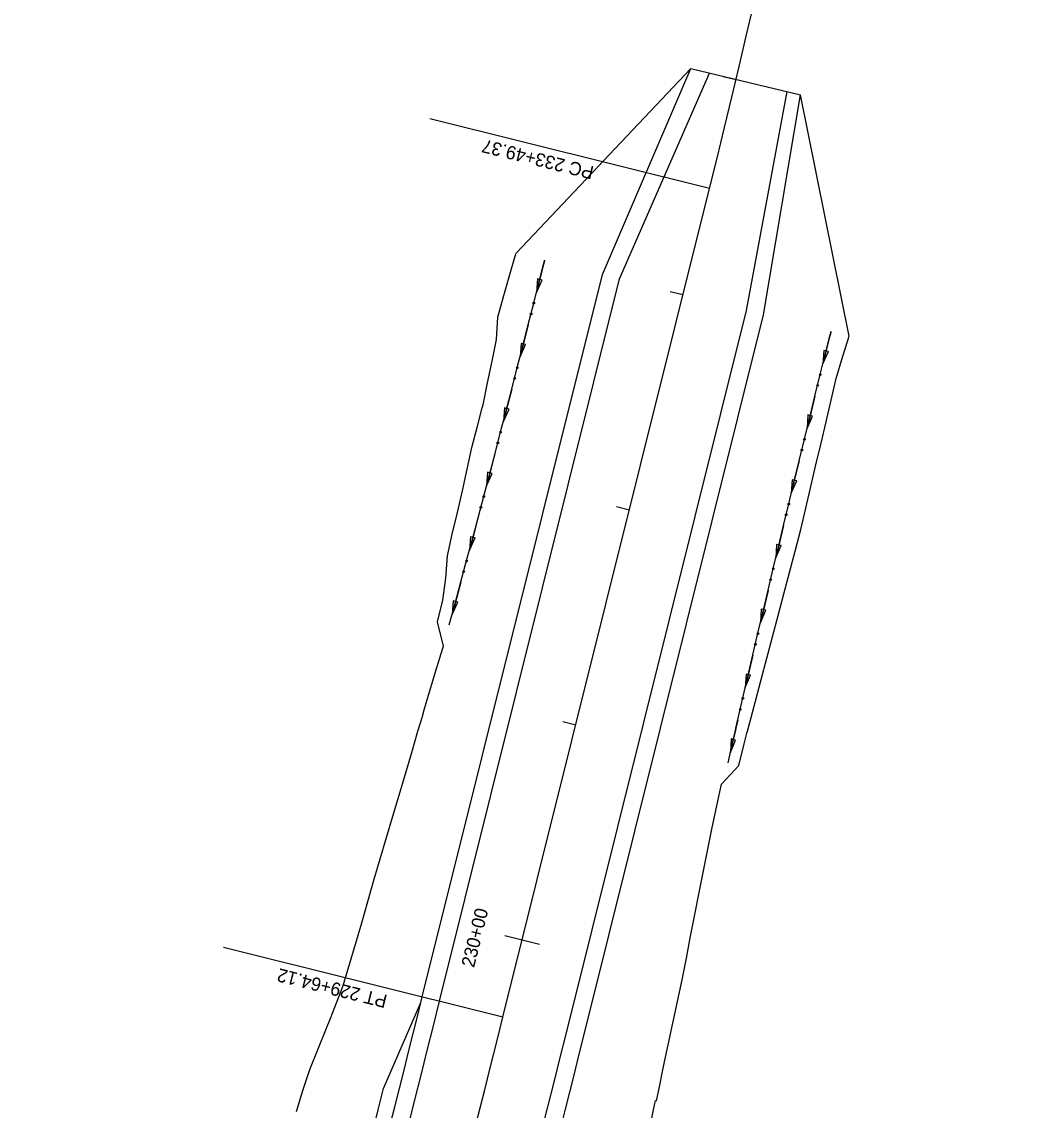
# Model space of a CAD drawing. Extents: x 1441466 to 1476381, y 2042742 to 2057194.
# Drawn here: x 1445981.2 to 1446430.9, y 2055828.9 to 2056319.9 of the extents above; entities that cross this region are included whole.
import ezdxf

# ---------------------------------------------------------------- set-up
doc = ezdxf.new("R2010")
doc.units = 0
for name, color, linetype in [('R_Horz Alg', 7, 'Continuous'), ('R_Horz Alg Annot', 7, 'Continuous'), ('R_Horz Alg Stationing', 7, 'Continuous'), ('R_Proposed Const Limits', 7, 'Continuous'), ('R_Proposed Road', 7, 'Continuous'), ('R_Shld', 7, 'Continuous'), ('R_Special Ditch', 7, 'Continuous')]:
    doc.layers.add(name, color=color, linetype=linetype)

msp = doc.modelspace()

# ---------------------------------------------------------------- linework, layer by layer
at = {"layer": 'R_Horz Alg'}
msp.add_line((1446198.35, 2055870.91), (1446291.55, 2056244.71), dxfattribs=at)
for centre, radius, start, end in [((1441386.21, 2057467.75), 5055.51, 346, 356.25), ((1423960.81, 2061415.35), 22918.31, 344.166667, 346)]:
    msp.add_arc(centre, radius, start, end, dxfattribs=at)
at = {"layer": 'R_Horz Alg Annot'}
for points in [[(1446291.55, 2056244.71), (1446165.41, 2056276.16)], [(1446198.35, 2055870.91), (1446072.21, 2055902.36)]]:
    msp.add_lwpolyline(points, dxfattribs=at)
at = {"layer": 'R_Horz Alg Stationing'}
for points in [[(1446297.71, 2056295.29), (1446303.55, 2056293.9)], [(1446273.78, 2056198.26), (1446279.6, 2056196.81)], [(1446249.59, 2056101.23), (1446255.41, 2056099.78)], [(1446225.4, 2056004.2), (1446231.22, 2056002.75)], [(1446199.26, 2055907.66), (1446214.79, 2055903.79)]]:
    msp.add_lwpolyline(points, dxfattribs=at)
at = {"layer": 'R_Proposed Const Limits'}
for points in [[(1446171.51, 2056038.25), (1446168.85, 2056049.22), (1446171.25, 2056058.93), (1446172.53, 2056068.92), (1446173.32, 2056079.02), (1446175.5, 2056088.79), (1446177.81, 2056098.52), (1446180.13, 2056108.24), (1446182.26, 2056118.02), (1446184.34, 2056127.81), (1446186.91, 2056137.47), (1446189.04, 2056145.78), (1446189.04, 2056145.78), (1446189.39, 2056147.16), (1446191.41, 2056156.96), (1446193.42, 2056166.77), (1446195.38, 2056176.59), (1446196.07, 2056186.72), (1446198.75, 2056196.36), (1446201.53, 2056205.97), (1446203.76, 2056213.66), (1446204.03, 2056214.62), (1446204.21, 2056215.22), (1446204.21, 2056215.23), (1446204.31, 2056215.58), (1446283.12, 2056298.78)], [(1446296.95, 2055976.06), (1446304.84, 2055984.39), (1446307.17, 2055994.12), (1446308.45, 2055998.96), (1446308.71, 2055999.92), (1446309.77, 2056003.78), (1446312.3, 2056013.45), (1446314.82, 2056023.13), (1446317.4, 2056032.79), (1446320.01, 2056042.45), (1446322.56, 2056052.12), (1446325.06, 2056061.8), (1446327.64, 2056071.47), (1446330.24, 2056081.12), (1446332.75, 2056090.8), (1446335.1, 2056100.53), (1446337.04, 2056108.88), (1446337.04, 2056108.89), (1446337.36, 2056110.27), (1446339.62, 2056120.01), (1446341.89, 2056129.75), (1446344.17, 2056139.49), (1446346.46, 2056149.22), (1446348.73, 2056158.96), (1446351.63, 2056168.55), (1446354.03, 2056176.19), (1446354.31, 2056177.15), (1446354.48, 2056177.75), (1446354.49, 2056177.76), (1446354.59, 2056178.11), (1446332.57, 2056286.97)], [(1446105.12, 2055828.3), (1446108.12, 2055837.82), (1446111.22, 2055847.32), (1446115.01, 2055856.64), (1446118.78, 2055865.97), (1446120.42, 2055870.04), (1446120.42, 2055870.05), (1446122.46, 2055875.32), (1446126.06, 2055884.7), (1446129.02, 2055894.25), (1446131.82, 2055903.86), (1446134.66, 2055913.46), (1446137.34, 2055923.1), (1446140.13, 2055932.71), (1446142.96, 2055942.31), (1446145.8, 2055951.91), (1446148.66, 2055961.5), (1446151.52, 2055971.09), (1446154.34, 2055980.7), (1446157.19, 2055990.29), (1446160.01, 2055999.89), (1446161.86, 2056006.11), (1446162.86, 2056009.49), (1446165.71, 2056019.08), (1446168.56, 2056028.68), (1446170, 2056033.47), (1446170.32, 2056034.42), (1446171.51, 2056038.25)], [(1446264.41, 2055819.15), (1446266.32, 2055829.02), (1446267.15, 2055833.32), (1446267.63, 2055833.21), (1446268.8, 2055838.74), (1446270.88, 2055848.56), (1446272.96, 2055858.37), (1446275.04, 2055868.15), (1446277.14, 2055877.93), (1446279.25, 2055887.71), (1446281.18, 2055897.54), (1446283.04, 2055907.38), (1446284.94, 2055917.21), (1446286.83, 2055927.05), (1446288.79, 2055936.87), (1446290.8, 2055946.67), (1446292.83, 2055956.47), (1446294.83, 2055966.28), (1446296.25, 2055972.6), (1446296.95, 2055976.06)]]:
    msp.add_lwpolyline(points, dxfattribs=at)
at = {"layer": 'R_Proposed Road'}
for p, q in [((1446243.22, 2056205.88), (1446283.12, 2056298.78)), ((1446250.98, 2056203.95), (1446291.6, 2056296.75)), ((1446283.12, 2056298.78), (1446332.57, 2056286.97)), ((1446308.23, 2056189.67), (1446326.65, 2056288.39)), ((1446315.99, 2056187.74), (1446332.57, 2056286.97)), ((1446161.96, 2055879.98), (1446243.22, 2056205.88)), ((1446169.72, 2055878.05), (1446250.98, 2056203.95)), ((1446226.97, 2055863.77), (1446308.23, 2056189.67)), ((1446234.73, 2055861.84), (1446315.99, 2056187.74))]:
    msp.add_line(p, q, dxfattribs=at)
for radius, start in [(22880.81, 345.318723), (22888.81, 344.166667), (22947.81, 344.166667), (22955.81, 345.318159)]:
    msp.add_arc((1423960.81, 2061415.35), radius, start, 346, dxfattribs=at)
at = {"layer": 'R_Shld'}
for p, q in [((1446144.43, 2055838.72), (1446161.36, 2055877.56)), ((1446102.07, 2055658.96), (1446142, 2055829.05))]:
    msp.add_line(p, q, dxfattribs=at)
msp.add_arc((1423961.31, 2061417.29), 22873.81, 345.85909, 345.88409, dxfattribs=at)
at = {"layer": 'R_Special Ditch'}
for p, q in [((1446213.92, 2056203.91), (1446213.48, 2056197.84)), ((1446213.48, 2056197.84), (1446215.98, 2056203.4)), ((1446215.98, 2056203.4), (1446213.92, 2056203.91)), ((1446206.53, 2056174.8), (1446206.07, 2056168.73)), ((1446206.07, 2056168.73), (1446208.58, 2056174.28)), ((1446208.58, 2056174.28), (1446206.53, 2056174.8)), ((1446343.18, 2056171.68), (1446342.76, 2056165.6)), ((1446342.76, 2056165.6), (1446345.24, 2056171.17)), ((1446345.24, 2056171.17), (1446343.18, 2056171.68)), ((1446199.04, 2056145.72), (1446198.55, 2056139.65)), ((1446198.55, 2056139.65), (1446201.09, 2056145.19)), ((1446201.09, 2056145.19), (1446199.04, 2056145.72)), ((1446335.98, 2056142.52), (1446335.58, 2056136.44)), ((1446335.58, 2056136.44), (1446338.03, 2056142.01)), ((1446338.03, 2056142.01), (1446335.98, 2056142.52)), ((1446191.44, 2056116.66), (1446190.93, 2056110.59)), ((1446190.93, 2056110.59), (1446193.49, 2056116.12)), ((1446193.49, 2056116.12), (1446191.44, 2056116.66)), ((1446328.88, 2056113.33), (1446328.49, 2056107.25)), ((1446328.49, 2056107.25), (1446330.94, 2056112.83)), ((1446330.94, 2056112.83), (1446328.88, 2056113.33)), ((1446183.74, 2056087.63), (1446183.21, 2056081.56)), ((1446183.21, 2056081.56), (1446185.79, 2056087.08)), ((1446185.79, 2056087.08), (1446183.74, 2056087.63)), ((1446321.83, 2056084.12), (1446321.47, 2056078.04)), ((1446321.47, 2056078.04), (1446323.89, 2056083.63)), ((1446323.89, 2056083.63), (1446321.83, 2056084.12)), ((1446175.94, 2056058.63), (1446175.39, 2056052.56)), ((1446175.39, 2056052.56), (1446177.99, 2056058.07)), ((1446177.99, 2056058.07), (1446175.94, 2056058.63)), ((1446314.88, 2056054.9), (1446314.54, 2056048.81)), ((1446314.54, 2056048.81), (1446316.94, 2056054.41)), ((1446316.94, 2056054.41), (1446314.88, 2056054.9)), ((1446308.04, 2056025.64), (1446307.72, 2056019.56)), ((1446307.72, 2056019.56), (1446310.1, 2056025.17)), ((1446310.1, 2056025.17), (1446308.04, 2056025.64)), ((1446301.3, 2055996.37), (1446301, 2055990.28)), ((1446303.36, 2055995.9), (1446301.3, 2055996.37)), ((1446301, 2055990.28), (1446303.36, 2055995.9))]:
    msp.add_line(p, q, dxfattribs=at)
for points in [[(1446174.13, 2056047.9), (1446176.75, 2056057.56), (1446179.36, 2056067.21), (1446181.96, 2056076.87), (1446184.55, 2056086.53), (1446187.12, 2056096.2), (1446189.69, 2056105.86), (1446192.24, 2056115.53), (1446194.78, 2056125.2), (1446197.31, 2056134.88), (1446199.47, 2056143.18), (1446199.47, 2056143.18), (1446199.83, 2056144.56), (1446202.34, 2056154.24), (1446204.83, 2056163.92), (1446207.32, 2056173.61), (1446209.79, 2056183.3), (1446212.25, 2056192.99), (1446214.7, 2056202.69), (1446216.66, 2056210.44), (1446216.9, 2056211.41), (1446217.05, 2056212.01), (1446217.05, 2056212.02), (1446217.14, 2056212.38)], [(1446217.14, 2056212.38), (1446217.05, 2056212.02), (1446217.05, 2056212.01), (1446216.9, 2056211.41), (1446216.66, 2056210.44), (1446214.7, 2056202.69), (1446213.48, 2056197.84)], [(1446209.78, 2056183.26), (1446207.32, 2056173.61), (1446206.07, 2056168.73)], [(1446209.79, 2056183.3), (1446209.79, 2056183.3), (1446209.78, 2056183.26)], [(1446299.94, 2055985.62), (1446302.16, 2055995.37), (1446303.27, 2056000.25), (1446303.5, 2056001.22), (1446304.39, 2056005.12), (1446306.63, 2056014.87), (1446308.89, 2056024.61), (1446311.15, 2056034.35), (1446313.43, 2056044.09), (1446315.72, 2056053.83), (1446318.02, 2056063.56), (1446320.33, 2056073.29), (1446322.65, 2056083.02), (1446324.99, 2056092.74), (1446327.33, 2056102.46), (1446329.35, 2056110.8), (1446329.35, 2056110.8), (1446329.69, 2056112.18), (1446332.04, 2056121.9), (1446334.4, 2056131.62), (1446336.78, 2056141.33), (1446339.16, 2056151.04), (1446341.56, 2056160.75), (1446343.97, 2056170.46), (1446345.9, 2056178.22), (1446346.15, 2056179.19), (1446346.3, 2056179.79), (1446346.3, 2056179.8), (1446346.39, 2056180.16)], [(1446346.39, 2056180.16), (1446346.3, 2056179.8), (1446346.3, 2056179.79), (1446346.15, 2056179.19), (1446345.9, 2056178.22), (1446343.97, 2056170.46), (1446342.76, 2056165.6)], [(1446202.32, 2056154.17), (1446199.83, 2056144.56), (1446199.47, 2056143.18), (1446199.47, 2056143.18), (1446198.55, 2056139.65)], [(1446202.33, 2056154.2), (1446202.32, 2056154.17)], [(1446339.15, 2056151.01), (1446336.78, 2056141.33), (1446335.58, 2056136.44)], [(1446339.16, 2056151.04), (1446339.16, 2056151.04), (1446339.15, 2056151.01)], [(1446194.75, 2056125.1), (1446192.24, 2056115.53), (1446190.93, 2056110.59)], [(1446194.76, 2056125.13), (1446194.75, 2056125.1)], [(1446332.02, 2056121.83), (1446329.69, 2056112.18), (1446329.35, 2056110.8), (1446329.35, 2056110.8), (1446328.49, 2056107.25)], [(1446332.03, 2056121.86), (1446332.02, 2056121.83)], [(1446187.08, 2056096.05), (1446184.55, 2056086.53), (1446183.21, 2056081.56)], [(1446187.09, 2056096.09), (1446187.08, 2056096.05)], [(1446324.96, 2056092.63), (1446322.65, 2056083.02), (1446321.47, 2056078.04)], [(1446324.97, 2056092.67), (1446324.96, 2056092.63)], [(1446179.31, 2056067.04), (1446176.75, 2056057.56), (1446175.39, 2056052.56)], [(1446179.32, 2056067.07), (1446179.31, 2056067.04)], [(1446317.99, 2056063.41), (1446315.72, 2056053.83), (1446314.54, 2056048.81)], [(1446317.99, 2056063.45), (1446317.99, 2056063.41)], [(1446311.11, 2056034.17), (1446308.89, 2056024.61), (1446307.72, 2056019.56)], [(1446311.12, 2056034.21), (1446311.11, 2056034.17)], [(1446304.34, 2056004.91), (1446303.5, 2056001.22), (1446303.27, 2056000.25), (1446302.16, 2055995.37), (1446301, 2055990.28)], [(1446304.35, 2056004.94), (1446304.34, 2056004.91)]]:
    msp.add_lwpolyline(points, dxfattribs=at)
for centre in [(1446212.29, 2056192.98), (1446211.05, 2056188.12), (1446204.86, 2056163.87), (1446203.61, 2056159.02), (1446341.59, 2056160.74), (1446340.39, 2056155.87), (1446197.33, 2056134.79), (1446196.06, 2056129.95), (1446334.43, 2056131.57), (1446333.24, 2056126.7), (1446189.69, 2056105.74), (1446188.41, 2056100.9), (1446327.35, 2056102.37), (1446326.17, 2056097.5), (1446181.95, 2056076.72), (1446180.65, 2056071.88), (1446320.34, 2056073.17), (1446319.18, 2056068.29), (1446313.43, 2056043.93), (1446312.29, 2056039.05), (1446306.63, 2056014.68), (1446305.5, 2056009.79)]:
    msp.add_circle(centre, 0.375, dxfattribs=at)

# ---------------------------------------------------------------- texts
at = {"layer": 'R_Horz Alg Annot'}
for s, p in [('PC 233+49.37', (1446239.78, 2056254.53)), ('PT 229+64.12', (1446146.55, 2055880.73))]:
    msp.add_text(s, height=6, rotation=166, dxfattribs=at).set_placement(p)
at = {"layer": 'R_Horz Alg Stationing'}
msp.add_text('230+00', height=6, rotation=76, dxfattribs=at).set_placement((1446185.29, 2055892.96))

doc.saveas('drawing.dxf')
